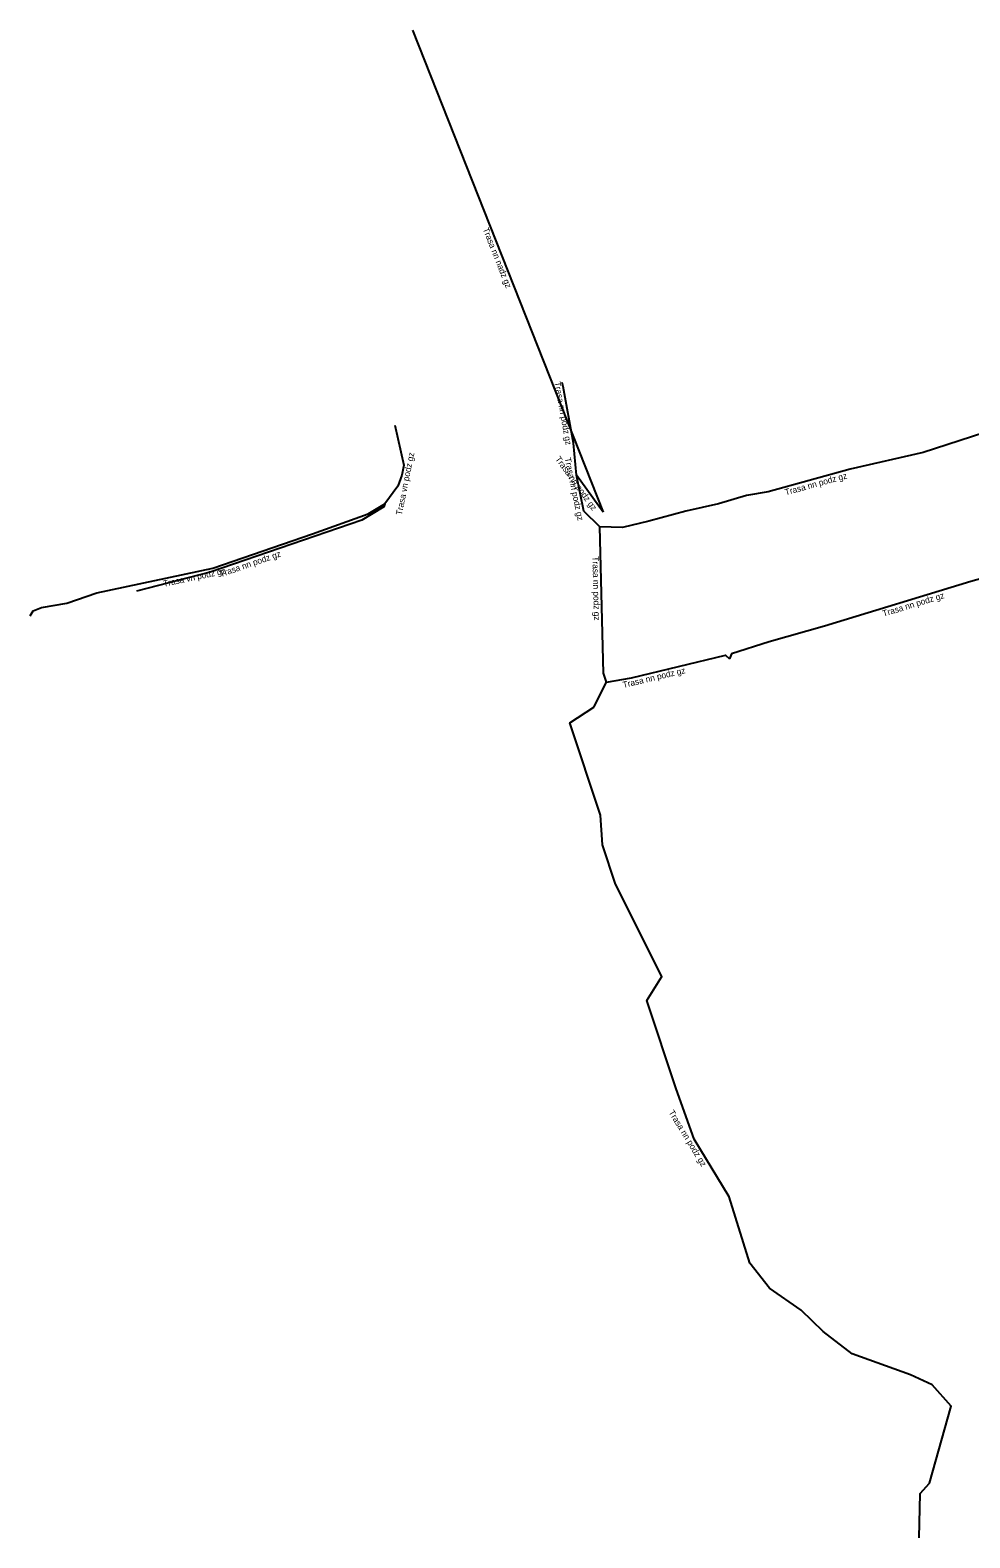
# Model space of a CAD drawing. Extents: x -690200 to -689130, y -975255 to -974631.
# Drawn here: x -690199.9 to -690124.3, y -975254.6 to -975133.2 of the extents above; entities that cross this region are included whole.
import ezdxf

# ---------------------------------------------------------------- set-up
doc = ezdxf.new("R2010")
doc.units = 0
for name, color, linetype in [('Popiskový text - Ostatní atributy Trasy', 7, 'Continuous'), ('Spojnice NN', 7, 'Continuous'), ('Spojnice VN', 7, 'Continuous')]:
    doc.layers.add(name, color=color, linetype=linetype)

msp = doc.modelspace()

# ---------------------------------------------------------------- linework, layer by layer
at = {"layer": 'Spojnice NN'}
for points in [[(-690169.13, -975133.25), (-690153.78, -975172.04)], [(-690155.94, -975169.05), (-690156.16, -975166.5), (-690157, -975161.93), (-690157.08, -975161.6)], [(-690117.16, -975163.8), (-690123.15, -975165.66), (-690128.04, -975167.23), (-690133.9, -975168.58), (-690140.5, -975170.4), (-690142.26, -975170.71), (-690144.51, -975171.38), (-690147.12, -975171.97), (-690150.1, -975172.77), (-690152.23, -975173.28), (-690154.06, -975173.21)], [(-690154.06, -975173.21), (-690155.33, -975171.95), (-690155.94, -975169.05)], [(-690153.78, -975172.04), (-690155.94, -975169.05)], [(-690171.35, -975171.36), (-690171.43, -975171.61), (-690173.22, -975172.68), (-690185.4, -975176.87), (-690191.33, -975178.39)], [(-690153.53, -975185.71), (-690153.76, -975185), (-690154.06, -975173.21)], [(-690111.56, -975175), (-690112.2, -975174.43), (-690119.52, -975176.46), (-690120.59, -975176.62), (-690124.2, -975177.63), (-690135.97, -975181.22), (-690140.43, -975182.47), (-690143.46, -975183.43), (-690143.63, -975183.85)], [(-690153.53, -975185.71), (-690151.5, -975185.37), (-690143.95, -975183.56), (-690143.63, -975183.85)], [(-690128.36, -975254.58), (-690128.27, -975251.01), (-690127.52, -975250.19), (-690125.78, -975243.98), (-690127.32, -975242.26), (-690129.06, -975241.47), (-690133.75, -975239.76), (-690136.07, -975237.98), (-690137.84, -975236.26), (-690140.4, -975234.49), (-690141.97, -975232.47), (-690143.64, -975227.14), (-690146.47, -975222.49), (-690147.91, -975218.44), (-690150.27, -975211.33), (-690149.07, -975209.4), (-690152.8, -975201.98), (-690153.83, -975198.81), (-690154, -975196.42), (-690156.46, -975188.98), (-690154.54, -975187.73), (-690153.53, -975185.71)]]:
    msp.add_lwpolyline(points, dxfattribs=at)
at = {"layer": 'Spojnice VN'}
for points in [[(-690170.54, -975165.04), (-690169.84, -975168.27), (-690170, -975169.06), (-690170.3, -975169.94), (-690171.35, -975171.36)], [(-690199.9, -975180.39), (-690199.67, -975179.97), (-690198.98, -975179.7), (-690196.95, -975179.36), (-690194.54, -975178.53), (-690185.19, -975176.55), (-690177.17, -975173.79), (-690172.71, -975172.18), (-690171.35, -975171.36)]]:
    msp.add_lwpolyline(points, dxfattribs=at)

# ---------------------------------------------------------------- texts
at = {"layer": 'Popiskový text - Ostatní atributy Trasy'}
for s, rotation, p in [('Trasa nn nadz gz', 291.5897, (-690163.49, -975149.26)), ('Trasa nn podz gz', 280.4212, (-690157.72, -975161.59)), ('Trasa vn podz gz', 78.5507, (-690169.99, -975172.31)), ('Trasa nn podz gz', 305.8446, (-690157.67, -975167.77)), ('Trasa nn podz gz', 281.8787, (-690156.89, -975167.7)), ('Trasa nn podz gz', 15.4166, (-690139.09, -975170.69)), ('Trasa nn podz gz', 18.9836, (-690184.56, -975177.27)), ('Trasa nn podz gz', 271.46, (-690154.65, -975175.6)), ('Trasa vn podz gz', 11.9566, (-690189.14, -975178.05)), ('Trasa nn podz gz', 16.9624, (-690131.22, -975180.45)), ('Trasa nn podz gz', 13.4805, (-690152.15, -975186.19)), ('Trasa nn podz gz', 301.3248, (-690148.54, -975220.34))]:
    msp.add_text(s, height=0.5, rotation=rotation, dxfattribs=at).set_placement(p)

doc.saveas('drawing.dxf')
